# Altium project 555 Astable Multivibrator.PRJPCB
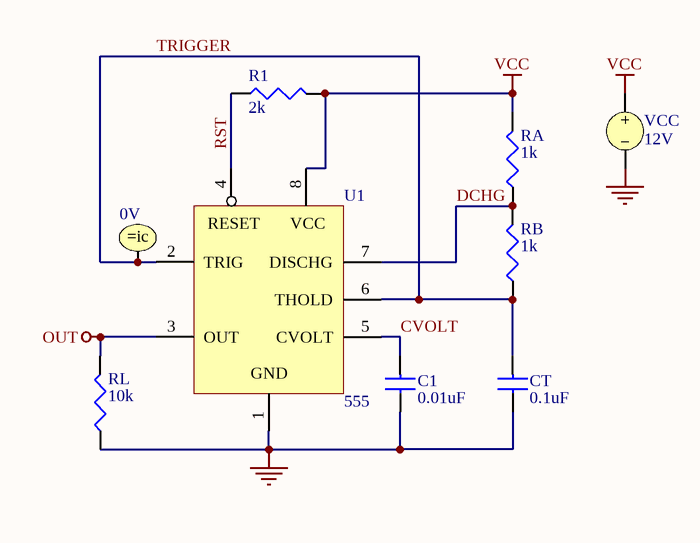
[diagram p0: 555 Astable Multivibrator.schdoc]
1 sheet, 9 parts. Net scope: global (net labels, ports and power ports of the same name join across sheets).

## Sheet 555 Astable Multivibrator.schdoc: 555 Astable Multivibrator
size A4; Organization: Altium Limited; Address1: L3, 12a Rodborough Rd; Address2: Frenchs Forest; Address3: NSW; Address4: Australia 2086; DocumentNumber: 1; SheetNumber: 1; SheetTotal: 1

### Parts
C1  0.01uF
CT  0.1uF
IC1  0V
R1  2k
RA  1k
RB  1k
RL  10k
U1  555
VCC  12V

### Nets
GND: C1.2 CT.2 RL.2(BOT) U1.1(GND) VCC.2
OUT: RL.1(TOP) U1.3(OUT)
VCC: R1.1(TOP) RA.1(TOP) U1.8(VCC) VCC.1
CVOLT: C1.1 U1.5(CVOLT)
DCHG: RA.2(BOT) RB.1(TOP) U1.7(DISCHG)
RST: R1.2(BOT) U1.4(RESET)
TRIGGER: CT.1 IC1.1 RB.2(BOT) U1.2(TRIG) U1.6(THOLD)

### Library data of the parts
C1 CT = CAP: Capacitor
IC1 = .IC: Initial Condition
R1 RA RB RL = RES: Resistor
U1 = 555: Timer
VCC = VSRC: Voltage Source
